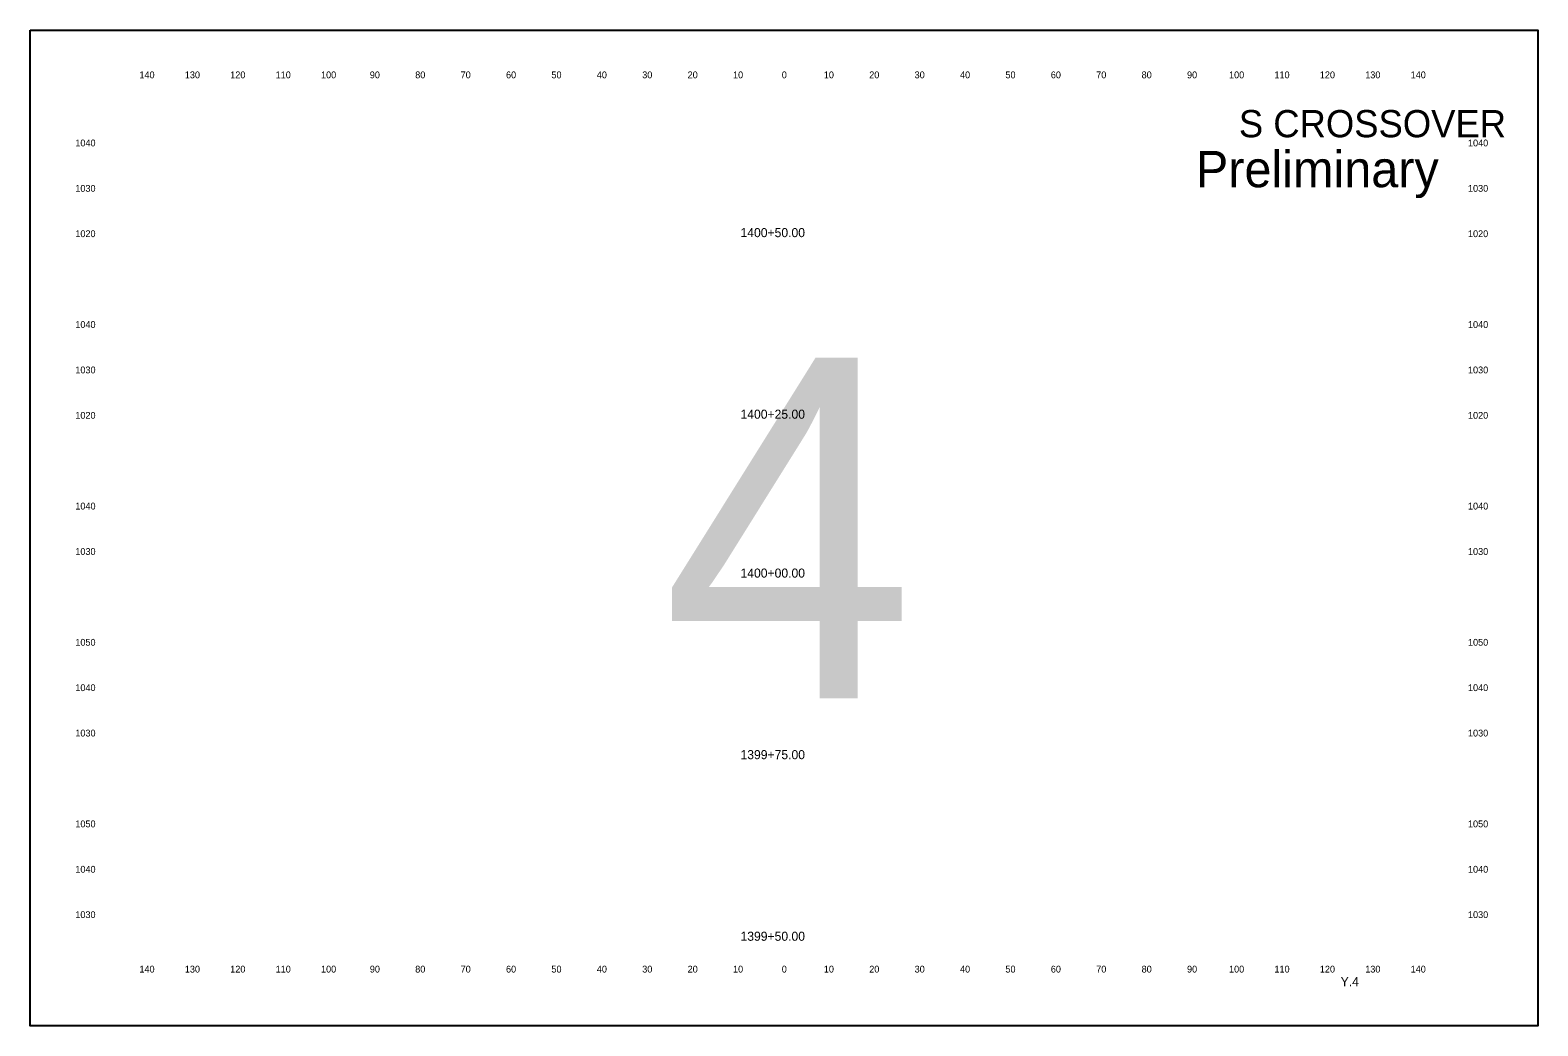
# Model space of a CAD drawing. Extents: x 10123 to 14768, y 9730 to 9950.
# Drawn here: x 11203.2 to 11535.3, y 9730.3 to 9949.6 of the extents above; entities that cross this region are included whole.
import ezdxf

# ---------------------------------------------------------------- set-up
doc = ezdxf.new("R2010")
doc.units = 0
for name, color, linetype in [('dsnTextCpn', 7, 'Continuous'), ('dsnTextCpnTitleSheetLocDesc', 7, 'Continuous'), ('dsnTextCpnTitleSheetPIN', 7, 'Continuous'), ('dsnTextCpnTitleSheetWorkType', 7, 'Continuous')]:
    doc.layers.add(name, color=color, linetype=linetype)

msp = doc.modelspace()

# ---------------------------------------------------------------- linework, layer by layer
at = {"layer": 'dsnTextCpnTitleSheetWorkType'}
msp.add_lwpolyline([(11203.21, 9949.6), (11535.29, 9949.6), (11535.29, 9730.26), (11203.21, 9730.26)], close=True, dxfattribs=at)

# ---------------------------------------------------------------- texts
at = {"layer": 'dsnTextCpn'}
for s, height, p in [('140', 1.5, (11227.27, 9939)), ('130', 1.5, (11237.27, 9939)), ('120', 1.5, (11247.27, 9939)), ('110', 1.5, (11257.27, 9939)), ('100', 1.5, (11267.27, 9939)), ('90', 1.5, (11278.02, 9939)), ('80', 1.5, (11288.02, 9939)), ('70', 1.5, (11298.02, 9939)), ('60', 1.5, (11308.02, 9939)), ('50', 1.5, (11318.02, 9939)), ('40', 1.5, (11328.02, 9939)), ('30', 1.5, (11338.02, 9939)), ('20', 1.5, (11348.02, 9939)), ('10', 1.5, (11358.02, 9939)), ('0', 1.5, (11368.76, 9939)), ('0', 1.5, (11368.76, 9939)), ('10', 1.5, (11378.02, 9939)), ('20', 1.5, (11388.02, 9939)), ('30', 1.5, (11398.02, 9939)), ('40', 1.5, (11408.02, 9939)), ('50', 1.5, (11418.02, 9939)), ('60', 1.5, (11428.02, 9939)), ('70', 1.5, (11438.02, 9939)), ('80', 1.5, (11448.02, 9939)), ('90', 1.5, (11458.02, 9939)), ('100', 1.5, (11467.27, 9939)), ('110', 1.5, (11477.27, 9939)), ('120', 1.5, (11487.27, 9939)), ('130', 1.5, (11497.27, 9939)), ('140', 1.5, (11507.27, 9939)), ('S CROSSOVER', 6, (11469.44, 9926)), ('1040', 1.5, (11213.15, 9924)), ('1040', 1.5, (11519.9, 9924)), ('1030', 1.5, (11213.15, 9914)), ('1030', 1.5, (11519.9, 9914)), ('1020', 1.5, (11213.15, 9904)), ('1400+50.00', 2, (11359.67, 9904)), ('1020', 1.5, (11519.9, 9904)), ('1040', 1.5, (11213.15, 9884)), ('1040', 1.5, (11519.9, 9884)), ('1030', 1.5, (11213.15, 9874)), ('1030', 1.5, (11519.9, 9874)), ('1020', 1.5, (11213.15, 9864)), ('1400+25.00', 2, (11359.67, 9864)), ('1020', 1.5, (11519.9, 9864)), ('1040', 1.5, (11213.15, 9844)), ('1040', 1.5, (11519.9, 9844)), ('1030', 1.5, (11213.15, 9834)), ('1030', 1.5, (11519.9, 9834)), ('1400+00.00', 2, (11359.67, 9829)), ('1050', 1.5, (11213.15, 9814)), ('1050', 1.5, (11519.9, 9814)), ('1040', 1.5, (11213.15, 9804)), ('1040', 1.5, (11519.9, 9804)), ('1030', 1.5, (11213.15, 9794)), ('1030', 1.5, (11519.9, 9794)), ('1399+75.00', 2, (11359.67, 9789)), ('1050', 1.5, (11213.15, 9774)), ('1050', 1.5, (11519.9, 9774)), ('1040', 1.5, (11213.15, 9764)), ('1040', 1.5, (11519.9, 9764)), ('1030', 1.5, (11213.15, 9754)), ('1030', 1.5, (11519.9, 9754)), ('1399+50.00', 2, (11359.67, 9749)), ('140', 1.5, (11227.27, 9742)), ('130', 1.5, (11237.27, 9742)), ('120', 1.5, (11247.27, 9742)), ('110', 1.5, (11257.27, 9742)), ('100', 1.5, (11267.27, 9742)), ('90', 1.5, (11278.02, 9742)), ('80', 1.5, (11288.02, 9742)), ('70', 1.5, (11298.02, 9742)), ('60', 1.5, (11308.02, 9742)), ('50', 1.5, (11318.02, 9742)), ('40', 1.5, (11328.02, 9742)), ('30', 1.5, (11338.02, 9742)), ('20', 1.5, (11348.02, 9742)), ('10', 1.5, (11358.02, 9742)), ('0', 1.5, (11368.76, 9742)), ('0', 1.5, (11368.76, 9742)), ('10', 1.5, (11378.02, 9742)), ('20', 1.5, (11388.02, 9742)), ('30', 1.5, (11398.02, 9742)), ('40', 1.5, (11408.02, 9742)), ('50', 1.5, (11418.02, 9742)), ('60', 1.5, (11428.02, 9742)), ('70', 1.5, (11438.02, 9742)), ('80', 1.5, (11448.02, 9742)), ('90', 1.5, (11458.02, 9742)), ('100', 1.5, (11467.27, 9742)), ('110', 1.5, (11477.27, 9742)), ('120', 1.5, (11487.27, 9742)), ('130', 1.5, (11497.27, 9742)), ('140', 1.5, (11507.27, 9742))]:
    msp.add_text(s, height=height, dxfattribs=at).set_placement(p)
at = {"layer": 'dsnTextCpnTitleSheetLocDesc'}
msp.add_text('Preliminary', height=8, dxfattribs=at).set_placement((11459.97, 9915))
at = {"layer": 'dsnTextCpnTitleSheetPIN'}
msp.add_text('Y.4', height=2, dxfattribs=at).set_placement((11491.86, 9739))
at = {"layer": 'dsnTextCpnTitleSheetWorkType'}
msp.add_text('4', height=75, dxfattribs=at).set_placement((11342.3, 9802.43))

doc.saveas('drawing.dxf')
